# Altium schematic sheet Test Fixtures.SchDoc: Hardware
size 431 x 279 mm; Date: Not shown in title block; ApprovedBy: Not shown in title block; CheckedBy: Not shown in title block; Author: Not shown in title block; CompanyName: Not shown in title block; DrawnBy: T Zhou; Engineer: Not shown in title block; Organization: Not shown in title block; Address1: Not shown in title block; Address2: Not shown in title block; Address3: Not shown in title block; Address4: Not shown in title block; DocumentNumber: 6; Revision: Use project parameter SCH_Rev; SheetNumber: 4; SheetTotal: 4; PageSetup: Record=PageOptions¦CenterHorizontal=True¦CenterVertical=True¦PrintScale=1.00¦XCorrection=1.00¦YCorrection=1.00¦PrintKind=0¦BorderSize=5000000¦LeftOffset=0¦BottomOffset=0¦Orientation=2¦PaperLength=1000¦PaperWidth=1000¦Scale=100¦PaperSource=15¦PrintQuality=600¦MediaType=1¦DitherType=10¦PaperKind=Letter¦PrintScaleMode=1
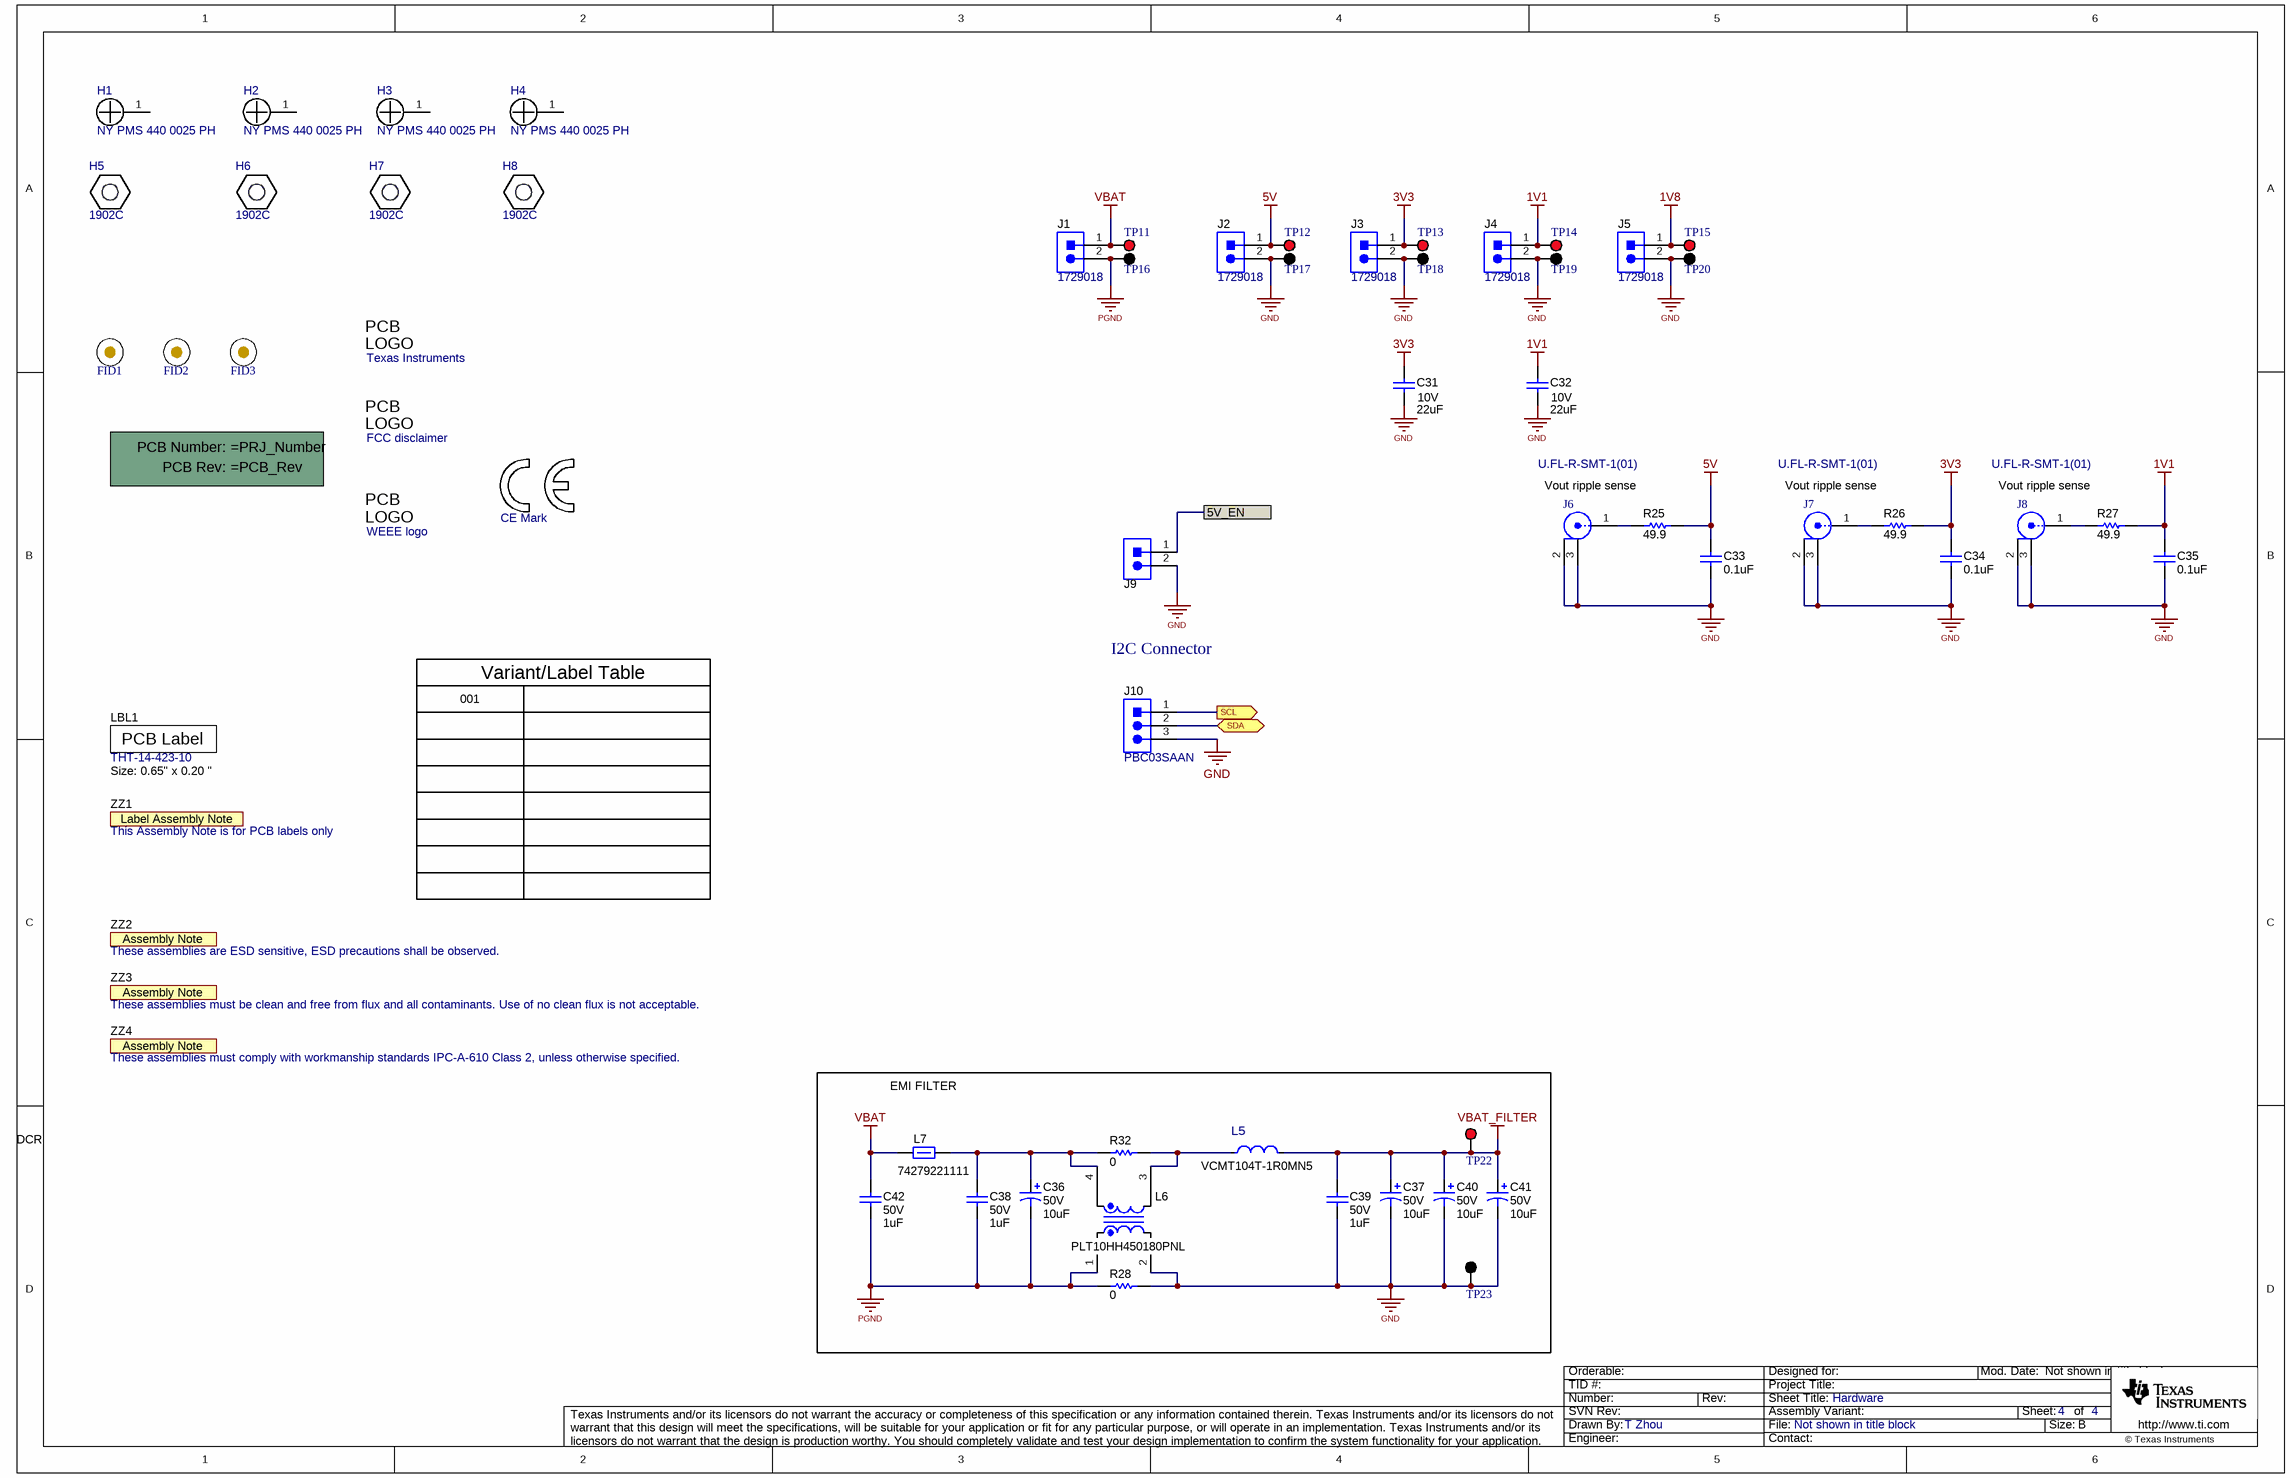
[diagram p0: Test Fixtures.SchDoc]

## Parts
!PCB1  Printed Circuit Board  (value not drawn)  (mechanical)
C31  VDC_V: 10V  ValueDisplayed: 22uF  [1206_180]  (hidden comment: GCM31CR71A226KE02)
C32  VDC_V: 10V  ValueDisplayed: 22uF  [1206_180]  (hidden comment: GCM31CR71A226KE02)
C33  ValueDisplayed: 0.1uF  [0402S]  (hidden comment: CGA2B3X7R1H104K050BB)
C34  ValueDisplayed: 0.1uF  [0402S]  (hidden comment: CGA2B3X7R1H104K050BB)
C35  ValueDisplayed: 0.1uF  [0402S]  (hidden comment: CGA2B3X7R1H104K050BB)
C36  VDC_V: 50V  ValueDisplayed: 10uF  [CAPSMT_62_F61]  (hidden comment: 50SVPF10M)
C37  VDC_V: 50V  ValueDisplayed: 10uF  [CAPSMT_62_F61]  (hidden comment: 50SVPF10M)
C38  VDC_V: 50V  ValueDisplayed: 1uF  [0805_HV]  (hidden comment: C0805C105K5RACTU)
C39  VDC_V: 50V  ValueDisplayed: 1uF  [0805_HV]  (hidden comment: C0805C105K5RACTU)
C40  VDC_V: 50V  ValueDisplayed: 10uF  [CAPSMT_62_F61]  (hidden comment: 50SVPF10M)
C41  VDC_V: 50V  ValueDisplayed: 10uF  [CAPSMT_62_F61]  (hidden comment: 50SVPF10M)
C42  VDC_V: 50V  ValueDisplayed: 1uF  [0805_HV]  (hidden comment: C0805C105K5RACTU)
FID1  Fiducial  [Fiducial10-20]  (value not drawn)
FID2  Fiducial  [Fiducial10-20]  (value not drawn)
FID3  Fiducial  [Fiducial10-20]  (value not drawn)
H1  NY PMS 440 0025 PH  [NY PMS 440 0025 PH]
H2  NY PMS 440 0025 PH  [NY PMS 440 0025 PH]
H3  NY PMS 440 0025 PH  [NY PMS 440 0025 PH]
H4  NY PMS 440 0025 PH  [NY PMS 440 0025 PH]
H5  1902C  [Keystone_1902C]
H6  1902C  [Keystone_1902C]
H7  1902C  [Keystone_1902C]
H8  1902C  [Keystone_1902C]
J1  1729018  [Phoenix_1729018]
J2  1729018  [Phoenix_1729018]
J3  1729018  [Phoenix_1729018]
J4  1729018  [Phoenix_1729018]
J5  1729018  [Phoenix_1729018]
J6  U.FL-R-SMT-1(01)  [CONN_UFL-R-SMT-1]
J7  U.FL-R-SMT-1(01)  [CONN_UFL-R-SMT-1]
J8  U.FL-R-SMT-1(01)  [CONN_UFL-R-SMT-1]
J9  HTSW-102-07-G-S  [Samtec_HTSW-102-07-G-S]  (value not drawn)
J10  PBC03SAAN  [PBC03SAAN]
L5  VCMT104T-4R7MN5  [FP-VCMT104T-4R7MN5_SMD_10MM85_10MM0-MFG]  (value not drawn)
L6  PLT10HH501100PNL  [MuRata_PLT10H]  (value not drawn)
L7  74279221111  [1206]
LBL1  THT-14-423-10  Note: Size: 0.65" x 0.20 "  [Label_650x200]
Logo1  Texas Instruments  [TI_Stacked_Overlay_Small]  (no BOM)
Logo2  FCC disclaimer  [FCC_disclaimer]  (no BOM)
Logo3  CE Mark  [CE_Mark_5mm]  (no BOM)
Logo4  WEEE logo  [WEEE_Minimum]  (no BOM)
R25  ValueDisplayed: 49.9  [0402S]  (hidden comment: CRCW040249R9FKED)
R26  ValueDisplayed: 49.9  [0402S]  (hidden comment: CRCW040249R9FKED)
R27  ValueDisplayed: 49.9  [0402S]  (hidden comment: CRCW040249R9FKED)
R28  ValueDisplayed: 0  [0805_HV]  (hidden comment: CRCW08050000Z0EA)
R32  ValueDisplayed: 0  [0805_HV]  (hidden comment: CRCW08050000Z0EA)
TP11  5000  [Keystone5000]  (value not drawn)
TP12  5000  [Keystone5000]  (value not drawn)
TP13  5000  [Keystone5000]  (value not drawn)
TP14  5000  [Keystone5000]  (value not drawn)
TP15  5000  [Keystone5000]  (value not drawn)
TP16  5001  [Keystone5001]  (value not drawn)
TP17  5001  [Keystone5001]  (value not drawn)
TP18  5001  [Keystone5001]  (value not drawn)
TP19  5001  [Keystone5001]  (value not drawn)
TP20  5001  [Keystone5001]  (value not drawn)
TP22  5000  [Keystone5000]  (value not drawn)
TP23  5001  [Keystone5001]  (value not drawn)
ZZ1  This Assembly Note is for PCB labels only  [AssemblyNoteLabel]  (no BOM)
ZZ2  These assemblies are ESD sensitive, ESD precautions shall be observed.  [AssemblyNote]  (no BOM)
ZZ3  These assemblies must be clean and free from flux and all contaminants. Use of no clean flux is not acceptable.  [AssemblyNote]  (no BOM)
ZZ4  These assemblies must comply with workmanship standards IPC-A-610 Class 2, unless otherwise specified.  [AssemblyNote]  (no BOM)

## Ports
5V_EN, SCL (out), SDA (bidir)

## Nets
1V1: C32.1 C35.2 J4.1 R27.2 TP14.1
1V8: J5.1 TP15.1
3V3: C31.1 C34.2 J3.1 R26.2 TP13.1
5V: C33.2 J2.1 R25.2 TP12.1
GND: C31.2 C32.2 C33.1 C34.1 C35.1 C37.2(-) C39.1 C40.2(-) C41.2(-) J2.2 J3.2 J4.2 J5.2 J6.2 J6.3 J7.2 J7.3 J8.2 J8.3 J9.2 J10.3 L6.2 R28.2 TP17.1 TP18.1 TP19.1 TP20.1 TP23.1
PGND: C36.2(-) C38.1 C42.1 J1.2 L6.1 R28.1 TP16.1
VBAT: C42.2 J1.1 L7.1 TP11.1
VBAT_FILTER: C37.1(+) C39.2 C40.1(+) C41.1(+) L5.2 TP22.1
5V_EN: J9.1 ; port 5V_EN
SCL: J10.1 ; port SCL
SDA: J10.2 ; port SDA
NetC36_1: C36.1(+) C38.2 L6.4 L7.2 R32.1
NetJ6_1: J6.1 R25.1
NetJ7_1: J7.1 R26.1
NetJ8_1: J8.1 R27.1
NetL5_1: L5.1 L6.3 R32.2

Not connected (* = marked no-connect by the designer): H1 1; H2 1; H3 1; H4 1

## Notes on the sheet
- Vout ripple sense
- 001
- Variant/Label Table
- I2C Connector
- EMI FILTER
- DCR
- (near L5) VCMT104T-1R0MN5
- (near L6) PLT10HH450180PNL

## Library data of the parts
!PCB1 = CMP-0003618-2: Manufacturer: Any
C31 C32 = CMP-0008811-2: CAP, CERM, 22 uF, 10 V, +/- 10%, X7R, AEC-Q200 Grade 1, 1206; Manufacturer: MuRata; TaMin_C: -55°C; Polarized: N; SizeAreaWB_mm2: 10.92; Value1: Unknown; U/M: EA; Value: 22uF; TaMax_C: 125°C; SizeZ_mm: 1.8; SizeX_mm: 3.2; SizeY_mm: 1.6; Cap_Case: 1206; SizeArea_mm2: 5.12; AEC Qualified: Y; Cap_F: 22µF; AEC Grade: 1; AEC Category: Q200
C33-C35 = CMP-0006325-2: CAP, CERM, 0.1 uF, 50 V, +/- 10%, X7R, AEC-Q200 Grade 1, 0402; Manufacturer: TDK; TaMin_C: -55°C; ESR_ohm: 0.039064; Polarized: N; SizeAreaWB_mm2: 3; Value1: 0.039064 ohm; U/M: EA; Value: 0.1uF; TaMax_C: 125°C; SizeZ_mm: 0.6; SizeX_mm: 1; SizeY_mm: 0.5; Cap_Case: 0402; Value2: 50V; AEC Qualified: Y; Cap_F: 100nF; IRMS_A: 814.669mA; AEC Category: Q200
C36 C37 C40 C41 = CMP-0012141-3: CAP, Aluminum Polymer, 10 uF, 50 V, +/- 20%, 0.04 ohm, F61 SMD; Manufacturer: Panasonic; TaMin_C: -55°C; ESR_ohm: 0.04; Polarized: Y; SizeAreaWB_mm2: 73.96; Value: 10uF; TaMax_C: 105°C; SizeZ_mm: 5.8; SizeX_mm: 6.6; SizeArea_mm2: 43.56; CompType: Capacitor; Cap_F: 10µF; IRMS_A: 2.5A; AEC Category: Q200
C38 C39 C42 = CMP-0007730-2: CAP, CERM, 1 uF, 50 V, +/- 10%, X7R, 0805; Manufacturer: Kemet; TaMin_C: -55°C; Polarized: N; SizeAreaWB_mm2: 6.75; Value1: Unknown; U/M: EA; Value: 1uF; TaMax_C: 125°C; SizeZ_mm: 1.45; SizeX_mm: 2; SizeY_mm: 1.25; Cap_Case: 0805; SizeArea_mm2: 2.5; Cap_F: 1µF; AEC Category: Q200
FID1-FID3 = CMP-0077181-1: Fiducial mark.  There is nothing to buy or mount.
H1-H4 = CMP-0003617-1: Machine Screw, Round, #4-40 x 1/4, Nylon, Philips panhead; Manufacturer: B&F Fastener Supply; CompType: Hardware
H5-H8 = CMP-0003610-1: Standoff, Hex, 0.5"L #4-40 Nylon; Manufacturer: Keystone; CompType: Hardware
J1-J5 = CMP-0055486-1: TERM BLOCK 2POS 5mm, TH; Manufacturer: Phoenix Contact; CT: TRUE; Green_REACh: Incomplete; CompType: Terminal Block; CNHeader: FALSE; Green_Lifecycle: Not Set
J6-J8 = CMP-0075320-1: Receptacle, Ultra Miniature Coaxial, Male Pin, 50 ohm, SMT; Manufacturer: Hirose Electric Co. Ltd.; CNHeader: False; Gender: Female; ContactFinish: Gold
J9 = CMP-0075483-1: Header, 100mil, 2x1, Gold, TH; Manufacturer: Samtec; Green_REACh: Passed; CT: False; Green_Lifecycle: Active; CNHeader: True
J10 = CMP-0002334-1: Header, 100mil, 3x1, Gold, TH; Manufacturer: Sullins Connector Solutions; Green_REACh: Incomplete; CT: FALSE; Green_Lifecycle: Not Set; CNHeader: TRUE
L5 = CMP-0089037-1: 4.7µH Unshielded  Inductor 11A 15mOhm Max Nonstandard; Manufacturer: Cyntec; Irms: 9.8A; DCR_ohm: 0.015; Material: Metal Dust; SizeZ_mm: 4mm; AEC Qualified: Yes; AEC Grade: Grade 0
L6 = CMP-0013217-2: Coupled inductor, 9 uH,  A, 0.0036 ohm, SMD; Manufacturer: MuRata; Value: 9uH; SizeZ_mm: 9.4; Ind_H: 9µH; DCR_ohm: 3.6m; SizeAreaWB_mm2: 128.14; SizeY_mm: 12.9; SizeArea_mm2: 85.14; SizeX_mm: 6.6
L7 = CMP-0003139-1: Ferrite Bead, 110 ohm @ 100 MHz, 5.4 A, 1206; Manufacturer: Wurth Elektronik; ZTyp@100MHz_Ohm: 110; SizeAreaWB_mm2: 10.92; DCR_ohm: 9.5m; Value1: 0.0095 ohm; Value: 110 ohm; Imax_A: 5.4A; SizeZ_mm: 1.35; SizeX_mm: 3.2; SizeY_mm: 1.6; SizeArea_mm2: 5.12; Ztyp@1GHz_Ohm: 43.549
LBL1 = CMP-0003625-1: Thermal Transfer Printable Labels, 0.650" W x 0.200" H - 10,000 per roll; Manufacturer: Brady
Logo1 = CMP-0074838-1: Texas Instrument Corporate Signature; SymbolCreator: a0412235; Lib Reference: TI_Logo
Logo2 = CMP-0074847-1: FCC_disclaimer
Logo3 = CMP-0074844-1: SymbolCreator: a0412235
Logo4 = CMP-0074769-1
R25-R27 = CMP-0026404-2: RES, 49.9, 1%, 0.063 W, AEC-Q200 Grade 0, 0402; Manufacturer: Vishay-Dale; Value: 49.9; Value_Code: 49R9; Power_W: 63mW; Value2: 0.063W; VDC_V: 50V; TempCo: 100 ppm/C; EIA_Code: E96; SizeArea_mm2: 0.5; SizeX_mm: 1; SizeZ_mm: 0.6; AEC Category: Q200; AEC Qualified: Y; AEC Grade: 0
R28 R32 = CMP-0020442-3: RES, 0, 5%, 0.125 W, AEC-Q200 Grade 0, 0805; Manufacturer: Vishay-Dale; Value: 0; Value_Code: 0000; Power_W: 125mW; Value2: 0.125W; VDC_V: 150V; TempCo: 200 ppm/C; EIA_Code: E24; SizeArea_mm2: 2.5; SizeX_mm: 2; SizeY_mm: 1.25; SizeZ_mm: 1.45; AEC Category: Q200; AEC Qualified: Y
TP11-TP15 TP22 = CMP-0055137-1: Test Point, Miniature, Red, TH; Manufacturer: Keystone; CNHeader: FALSE; Green_Lifecycle: Active; Green_REACh: Passed; ContactFinish: Silver; CT: TRUE
TP16-TP20 TP23 = CMP-0055138-1: Test Point, Miniature, Black, TH; Manufacturer: Keystone; CNHeader: FALSE; Green_Lifecycle: Active; Green_REACh: Passed; ContactFinish: Silver; CT: TRUE
ZZ1 = CMP-0003616-3
ZZ2 = CMP-0077236-1
ZZ3 = CMP-0077237-1
ZZ4 = CMP-0077238-1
